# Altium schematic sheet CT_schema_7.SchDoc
size 299 x 271 mm
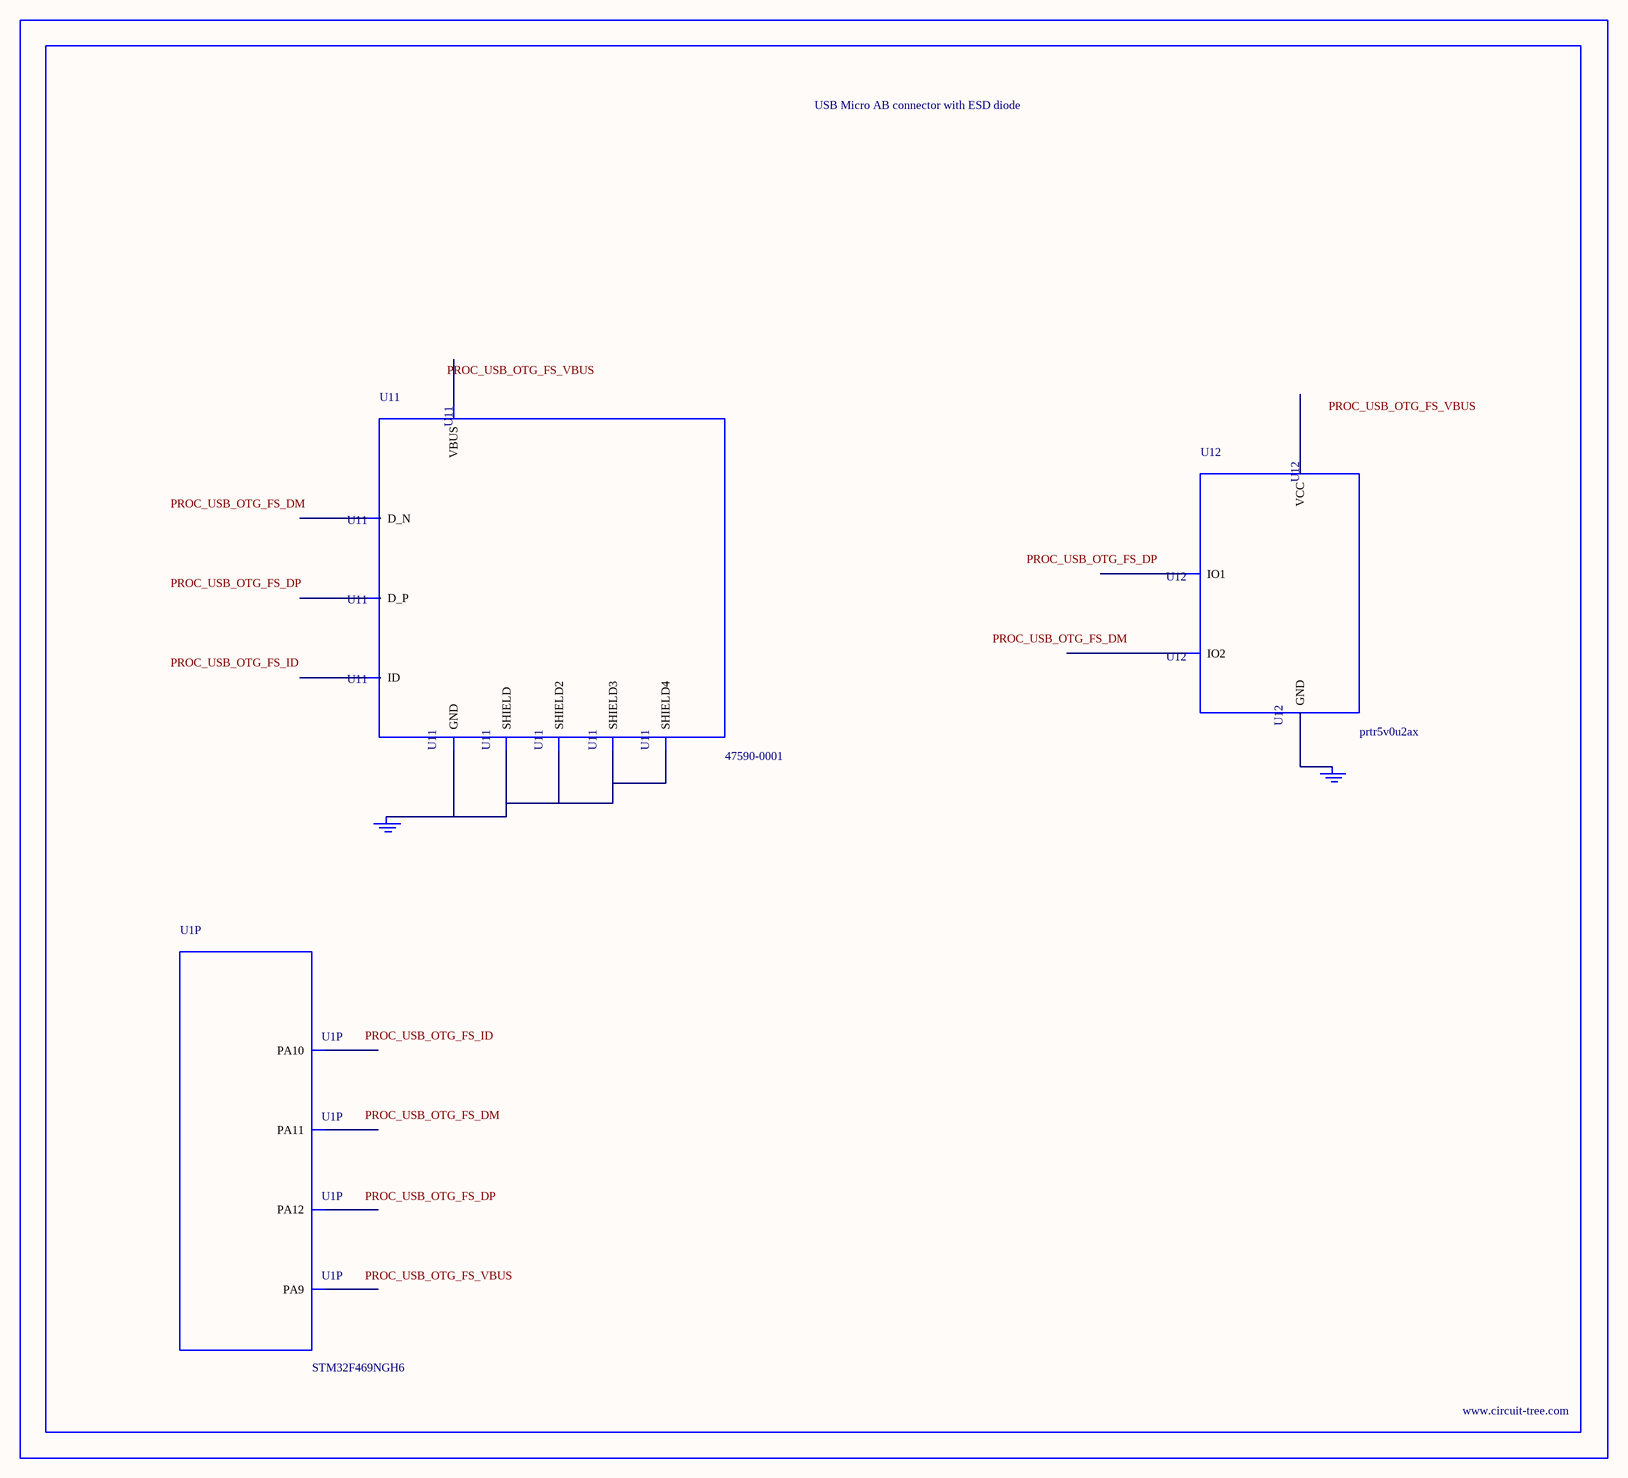
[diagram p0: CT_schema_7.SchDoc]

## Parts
BORDER6  (no value)
GND_INSTANCE_6_0  (no value)
GND_INSTANCE_6_1  (no value)
U1  STM32F469NGH6  [TFBGA216]  (part P of 16)
U11  47590-0001  [MICRO_USB_AB]
U12  prtr5v0u2ax  [SOT143B]

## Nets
NetGND_INSTANCE_6_0_0: GND_INSTANCE_6_0.0(GND) U11.5(GND) U11.6(SHIELD) U11.7(SHIELD2) U11.8(SHIELD3) U11.9(SHIELD4)
NetGND_INSTANCE_6_1_0: GND_INSTANCE_6_1.0(GND) U12.1(GND)

Not connected (* = marked no-connect by the designer): U1 B15(PA12) C15(PA11) D15(PA10) E15(PA9); U11 1(VBUS) 2(D_N) 3(D_P) 4(ID); U12 2(IO1) 3(IO2) 4(VCC)

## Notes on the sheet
- Labels drawn without touching a wire or pin: PROC_USB_OTG_FS_DM, PROC_USB_OTG_FS_DP, PROC_USB_OTG_FS_ID, PROC_USB_OTG_FS_VBUS

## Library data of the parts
BORDER6 = BORDER_PAGE6
GND_INSTANCE_6_0 GND_INSTANCE_6_1 = GND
